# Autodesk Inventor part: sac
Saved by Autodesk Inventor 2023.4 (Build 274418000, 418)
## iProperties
Created: 2011-01
Part Number: sac
Document SubType Name: Modeling
Designer: eric
Density: 1 g/cm^3
Material: Générique
Appearance: Par défaut
Author: eric
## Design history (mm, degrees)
node "Esquisse1"
node "Corps solides"
node "Corps surfaciques"
